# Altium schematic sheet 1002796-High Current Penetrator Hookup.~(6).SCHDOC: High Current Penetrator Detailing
size Tabloid; Organization: Monterey Bay Aquarium Research Institute; Address1: 7700 Sandholdt Rd; Address2: Moss Landing, CA 95039-9644; DocumentNumber: 1002796; Revision: Initial; SheetNumber: 1; CompanyName: MBARI; Engineer: Hans Thomas
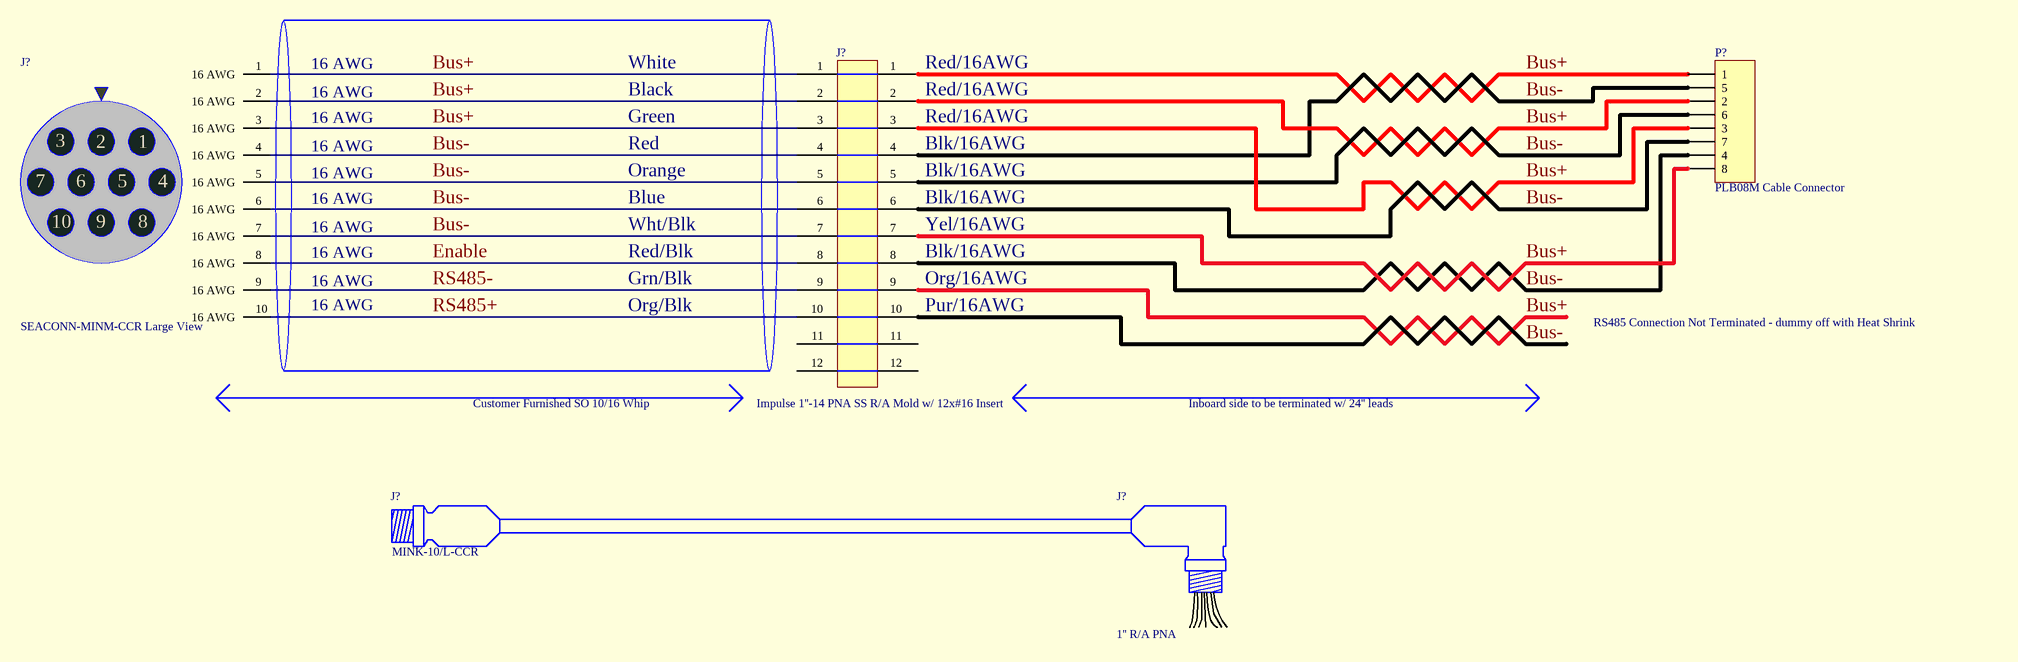
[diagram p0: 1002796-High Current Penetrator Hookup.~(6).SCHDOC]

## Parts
(Parts that share a designator on the sheet are numbered #1, #2 ... from top to bottom, then left to right.)
J?#1  Impulse 1''-14 PNA SS R/A Mold w/ 12x#16 Insert
J?#2  SEACONN-MINM-CCR Large View
J?#3  MINK-10/L-CCR
J?#4  1'' R/A PNA
P?  PLB08M Cable Connector  [HDR1X8]

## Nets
Bus+: J?#1.1 J?#1.2 J?#1.3 J?#1.7 J?#1.9 J?#2.1(16_AWG) J?#2.2(16_AWG) J?#2.3(16_AWG) P?.1 P?.2 P?.3 P?.8
Bus-: J?#1.4 J?#1.5 J?#1.6 J?#1.7 J?#1.8 J?#1.10 J?#2.4(16_AWG) J?#2.5(16_AWG) J?#2.6(16_AWG) J?#2.7(16_AWG) P?.4 P?.5 P?.6 P?.7
Enable: J?#1.8 J?#2.8(16_AWG)
RS485+: J?#1.10 J?#2.10(16_AWG)
RS485-: J?#1.9 J?#2.9(16_AWG)

Not connected (* = marked no-connect by the designer): J?#1 11 12

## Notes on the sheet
- 16 AWG
- Green
- White
- Black
- (near J?#1) Red/16AWG
- Red
- Orange
- (near J?#1) Blk/16AWG
- Red/Blk
- Wht/Blk
- Blue
- (near J?#1) Yel/16AWG
- Org/Blk
- Grn/Blk
- (near J?#1) Org/16AWG
- (near J?#1) Pur/16AWG
- RS485 Connection Not Terminated - dummy off with Heat Shrink
- Customer Furnished SO 10/16 Whip
- Inboard side to be terminated w/ 24'' leads

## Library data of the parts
J?#1 = Impulse PNA
J?#3 = CONN-MIN-CCR: Seacon MIN Connector CCR
J?#4 = CONN-MIN-PENE: Seacon MIN Penetrator
P? = Header 8: Header, 8-Pin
